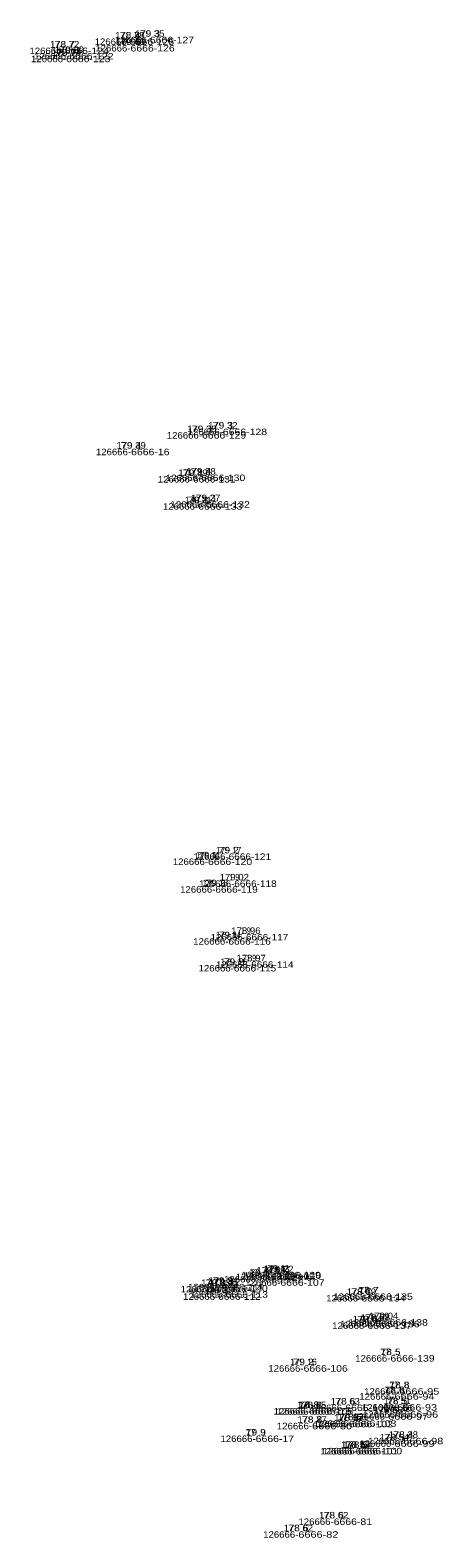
# Model space of a CAD drawing. Extents: x -598473 to -594209, y -1163589 to -1162143.
# Drawn here: x -594821.9 to -594726.9, y -1162489.7 to -1162142.5 of the extents above; entities that cross this region are included whole.
import ezdxf
from ezdxf.enums import TextEntityAlignment as Align

# ---------------------------------------------------------------- set-up
doc = ezdxf.new("R2010")
doc.units = 0
doc.header["$LTSCALE"] = 0.6
for name, color, linetype in [('57', 7, 'Continuous'), ('58', 7, 'Continuous'), ('61', 7, 'Continuous'), ('62', 7, 'Continuous')]:
    doc.layers.add(name, color=color, linetype=linetype)

msp = doc.modelspace()

# ---------------------------------------------------------------- texts
at = {"layer": '57'}
for s, width, p in [('78 8', 1.2, (-594798.928, -1162144.457)), ('79 5', 1.2, (-594798.778, -1162145.957)), ('79 3', 1.2, (-594794.328, -1162144.067)), ('78 7', 1.2, (-594813.928, -1162146.557)), ('78 7', 1.2, (-594813.578, -1162148.417)), ('79 3', 1.2, (-594812.848, -1162147.787)), ('79 3', 1.2, (-594782.338, -1162235.087)), ('79 3', 1.2, (-594777.528, -1162234.277)), ('79 4', 1.2, (-594798.638, -1162238.907)), ('79 4', 1.2, (-594784.408, -1162245.197)), ('79 4', 1.2, (-594782.538, -1162244.867)), ('79 3', 1.2, (-594783.218, -1162251.457)), ('79 3', 1.2, (-594781.488, -1162250.997)), ('79 1', 1.1, (-594780.9485, -1162333.247)), ('79 2', 1.2, (-594776.198, -1162332.087)), ('79 2', 1.2, (-594779.258, -1162339.637)), ('1 9', 0.65, (-594774.898, -1162338.307)), ('1 9', 0.65, (-594772.228, -1162350.637)), ('79 1', 1.1, (-594776.2485, -1162351.607)), ('1 9', 0.65, (-594771.018, -1162356.937)), ('79 2', 1.2, (-594775.008, -1162357.777)), ('79 1', 1.1, (-594769.1485, -1162429.377)), ('79 1', 1.1, (-594766.4685, -1162428.837)), ('79 1', 1.1, (-594765.1485, -1162428.427)), ('79 2', 1.2, (-594764.648, -1162428.547)), ('79 1', 1.1, (-594764.3085, -1162430.147)), ('79 3', 1.2, (-594779.148, -1162431.687)), ('79 3', 1.2, (-594778.598, -1162433.387)), ('79 3', 1.2, (-594777.468, -1162431.197)), ('79 3', 1.2, (-594777.368, -1162431.467)), ('79 3', 1.2, (-594776.918, -1162432.897)), ('78 7', 1.2, (-594745.678, -1162433.757)), ('78 7', 1.2, (-594744.008, -1162433.387)), ('78 6', 1.2, (-594744.278, -1162440.067)), ('78 7', 1.2, (-594742.448, -1162439.697)), ('1 9', 0.65, (-594740.538, -1162439.327)), ('78 5', 1.2, (-594738.978, -1162447.597)), ('79 2', 1.2, (-594758.968, -1162449.917)), ('78 6', 1.2, (-594738.038, -1162456.367)), ('78 8', 1.2, (-594736.928, -1162455.217)), ('78 8', 1.2, (-594757.728, -1162459.787)), ('78 8', 1.2, (-594757.098, -1162459.827)), ('78 6', 1.2, (-594749.368, -1162458.987)), ('78 6', 1.2, (-594739.498, -1162460.987)), ('78 5', 1.2, (-594737.448, -1162458.887)), ('78 6', 1.2, (-594737.198, -1162460.517)), ('78 8', 1.2, (-594756.998, -1162463.177)), ('78 6', 1.2, (-594748.558, -1162462.747)), ('78 6', 1.2, (-594747.778, -1162462.587)), ('79 9', 1.2, (-594769.9775, -1162466.117)), ('78 5', 1.2, (-594738.048, -1162467.237)), ('78 4', 1.2, (-594736.018, -1162466.647)), ('78 6', 1.2, (-594746.988, -1162468.987)), ('78 5', 1.2, (-594746.448, -1162468.957)), ('78 6', 1.2, (-594752.038, -1162485.207)), ('78 6', 1.2, (-594760.158, -1162488.157))]:
    msp.add_text(s, height=1.5, dxfattribs=dict(at, width=width)).set_placement(p, align=Align.CENTER)
at = {"layer": '58'}
for s, width, p in [('178 78', 1.1, (-594798.9285, -1162144.457)), ('179 49', 1.1, (-594798.7785, -1162145.957)), ('179 35', 1.1, (-594794.328, -1162144.067)), ('178 72', 1.1, (-594813.9285, -1162146.557)), ('178 74', 1.1, (-594813.5785, -1162148.417)), ('179 29', 1.1, (-594812.8485, -1162147.787)), ('179 35', 1.1, (-594782.338, -1162235.087)), ('179 32', 1.1, (-594777.528, -1162234.277)), ('179 39', 1.1, (-594798.6385, -1162238.907)), ('179 39', 1.1, (-594784.4085, -1162245.197)), ('179 38', 1.1, (-594782.538, -1162244.867)), ('179 27', 1.1, (-594781.488, -1162250.997)), ('179 11', 0.9, (-594780.9485, -1162333.247)), ('179 17', 0.95, (-594776.198, -1162332.087)), ('179 18', 0.95, (-594779.258, -1162339.637)), ('179 02', 1.1, (-594774.898, -1162338.307)), ('178 96', 1.1, (-594772.228, -1162350.637)), ('179 14', 0.95, (-594776.248, -1162351.607)), ('178 97', 1.1, (-594771.0185, -1162356.937)), ('179 09', 1.1, (-594766.4675, -1162428.837)), ('179 13', 0.95, (-594765.148, -1162428.427)), ('179 22', 1.1, (-594764.648, -1162428.547)), ('179 09', 1.1, (-594764.3075, -1162430.147)), ('179 33', 1.1, (-594779.148, -1162431.687)), ('179 34', 1.1, (-594777.468, -1162431.197)), ('179 35', 1.1, (-594777.368, -1162431.467)), ('179 35', 1.1, (-594776.918, -1162432.897)), ('178 69', 1.1, (-594745.678, -1162433.757)), ('178 64', 1.1, (-594744.2775, -1162440.067)), ('178 68', 1.1, (-594742.4475, -1162439.697)), ('179 04', 1.1, (-594740.538, -1162439.327)), ('178 75', 1.1, (-594757.0985, -1162459.827)), ('178 63', 1.1, (-594749.3675, -1162458.987)), ('178 56', 1.1, (-594739.498, -1162460.987)), ('178 56', 1.1, (-594737.198, -1162460.517)), ('178 77', 1.1, (-594756.9985, -1162463.177)), ('178 57', 1.1, (-594748.5585, -1162462.747)), ('178 56', 1.1, (-594747.778, -1162462.587)), ('178 54', 1.1, (-594738.0485, -1162467.237)), ('178 38', 1.1, (-594736.0185, -1162466.647)), ('178 55', 1.1, (-594746.9885, -1162468.987)), ('178 54', 1.1, (-594746.4485, -1162468.957)), ('178 62', 1.1, (-594752.0375, -1162485.207)), ('178 62', 1.1, (-594760.1575, -1162488.157))]:
    msp.add_text(s, height=1.5, dxfattribs=dict(at, width=width)).set_placement(p, align=Align.CENTER)
for s, p in [('179 31', (-594783.2175, -1162251.457)), ('179 16', (-594775.008, -1162357.777)), ('17 .1', (-594769.1475, -1162429.377)), ('179 31', (-594778.5975, -1162433.387)), ('17 .7', (-594744.008, -1162433.387)), ('17 .5', (-594738.978, -1162447.597)), ('179 16', (-594758.968, -1162449.917)), ('17 .6', (-594738.038, -1162456.367)), ('17 .8', (-594736.928, -1162455.217)), ('17 .8', (-594757.728, -1162459.787)), ('178 51', (-594737.448, -1162458.887)), ('17 .9', (-594769.9785, -1162466.117))]:
    msp.add_text(s, height=1.5, dxfattribs=at).set_placement(p, align=Align.CENTER)
at = {"layer": '61', "width": 1.1}
for p in [(-594798.928, -1162145.957), (-594794.328, -1162145.567), (-594813.928, -1162148.057), (-594812.848, -1162149.287), (-594798.778, -1162147.457), (-594813.578, -1162149.917), (-594777.528, -1162235.777), (-594782.338, -1162236.587), (-594798.638, -1162240.407), (-594782.538, -1162246.367), (-594784.408, -1162246.697), (-594783.218, -1162252.957), (-594781.488, -1162252.497), (-594780.948, -1162334.747), (-594776.198, -1162333.587), (-594774.898, -1162339.807), (-594779.258, -1162341.137), (-594776.248, -1162353.107), (-594772.228, -1162352.137), (-594775.008, -1162359.277), (-594771.018, -1162358.437), (-594766.468, -1162430.337), (-594765.148, -1162429.927), (-594764.648, -1162430.047), (-594779.148, -1162433.187), (-594777.468, -1162432.697), (-594777.368, -1162432.967), (-594769.148, -1162430.877), (-594764.308, -1162431.647), (-594778.598, -1162434.887), (-594776.918, -1162434.397), (-594745.678, -1162435.257), (-594744.008, -1162434.887), (-594740.538, -1162440.827), (-594744.278, -1162441.567), (-594742.448, -1162441.197), (-594758.968, -1162451.417), (-594738.978, -1162449.097), (-594738.038, -1162457.867), (-594736.928, -1162456.717), (-594757.728, -1162461.287), (-594757.098, -1162461.327), (-594749.368, -1162460.487), (-594737.448, -1162460.387), (-594756.998, -1162464.677), (-594748.558, -1162464.247), (-594747.778, -1162464.087), (-594739.498, -1162462.487), (-594737.198, -1162462.017), (-594769.978, -1162467.617), (-594738.048, -1162468.737), (-594736.018, -1162468.147), (-594746.988, -1162470.487), (-594746.448, -1162470.457), (-594752.038, -1162486.707), (-594760.158, -1162489.657)]:
    msp.add_text('126666-', height=1.5, dxfattribs=at).set_placement(p, align=Align.RIGHT)
at = {"layer": '62'}
for s, width, p in [('6666-125', 1.2, (-594798.928, -1162145.957)), ('6666-127', 1.2, (-594794.328, -1162145.567)), ('6666-124', 1.2, (-594813.928, -1162148.057)), ('6666-122', 1.2, (-594812.848, -1162149.287)), ('6666-126', 1.2, (-594798.778, -1162147.457)), ('6666-123', 1.2, (-594813.578, -1162149.917)), ('6666-128', 1.2, (-594777.528, -1162235.777)), ('6666-129', 1.2, (-594782.338, -1162236.587)), ('6666-16', 1.2, (-594798.638, -1162240.407)), ('6666-130', 1.2, (-594782.538, -1162246.367)), ('6666-131', 1.15, (-594784.408, -1162246.697)), ('6666-133', 1.2, (-594783.218, -1162252.957)), ('6666-132', 1.2, (-594781.488, -1162252.497)), ('6666-120', 1.2, (-594780.948, -1162334.747)), ('6666-121', 1.15, (-594776.198, -1162333.587)), ('6666-118', 1.15, (-594774.898, -1162339.807)), ('6666-119', 1.15, (-594779.258, -1162341.137)), ('6666-116', 1.15, (-594776.248, -1162353.107)), ('6666-117', 1.15, (-594772.228, -1162352.137)), ('6666-115', 1.15, (-594775.008, -1162359.277)), ('6666-114', 1.15, (-594771.018, -1162358.437)), ('6666-108', 1.2, (-594766.468, -1162430.337)), ('6666-109', 1.2, (-594765.148, -1162429.927)), ('6666-110', 1.15, (-594764.648, -1162430.047)), ('6666-141', 1.15, (-594779.148, -1162433.187)), ('6666-111', 1.1, (-594777.468, -1162432.697)), ('6666-140', 1.2, (-594777.368, -1162432.967)), ('6666-142', 1.2, (-594769.148, -1162430.877)), ('6666-107', 1.2, (-594764.308, -1162431.647)), ('6666-112', 1.15, (-594778.598, -1162434.887)), ('6666-113', 1.15, (-594776.918, -1162434.397)), ('6666-134', 1.2, (-594745.678, -1162435.257)), ('6666-135', 1.2, (-594744.008, -1162434.887)), ('6666-138', 1.2, (-594740.538, -1162440.827)), ('6666-137', 1.2, (-594744.278, -1162441.567)), ('6666-136', 1.2, (-594742.448, -1162441.197)), ('6666-106', 1.2, (-594758.968, -1162451.417)), ('6666-139', 1.2, (-594738.978, -1162449.097)), ('6666-94', 1.25, (-594738.038, -1162457.867)), ('6666-95', 1.25, (-594736.928, -1162456.717)), ('6666-105', 1.2, (-594757.728, -1162461.287)), ('6666-79', 1.25, (-594757.098, -1162461.327)), ('6666-104', 1.2, (-594749.368, -1162460.487)), ('6666-93', 1.25, (-594737.448, -1162460.387)), ('6666-80', 1.25, (-594756.998, -1162464.677)), ('6666-102', 1.2, (-594748.558, -1162464.247)), ('6666-103', 1.2, (-594747.778, -1162464.087)), ('6666-97', 1.25, (-594739.498, -1162462.487)), ('6666-96', 1.25, (-594737.198, -1162462.017)), ('6666-17', 1.2, (-594769.978, -1162467.617)), ('6666-99', 1.25, (-594738.048, -1162468.737)), ('6666-98', 1.25, (-594736.018, -1162468.147)), ('6666-101', 1.15, (-594746.988, -1162470.487)), ('6666-100', 1.2, (-594746.448, -1162470.457)), ('6666-81', 1.2, (-594752.038, -1162486.707)), ('6666-82', 1.25, (-594760.158, -1162489.657))]:
    msp.add_text(s, height=1.5, dxfattribs=dict(at, width=width)).set_placement(p)

doc.saveas('drawing.dxf')
